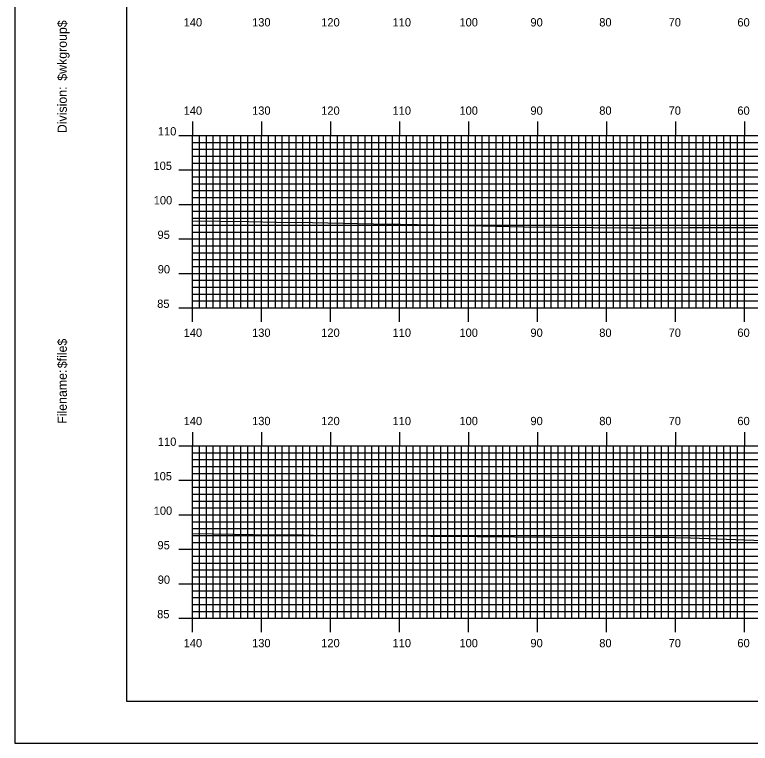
# Model space of a CAD drawing. Extents: x 1764546 to 1764889, y 442591 to 442811.
# Drawn here: x 1764545.6 to 1764652.2, y 442590.5 to 442696.2 of the extents above; entities that cross this region are included whole.
import ezdxf

# ---------------------------------------------------------------- set-up
doc = ezdxf.new("R2010")
doc.units = 0
for name, color, linetype in [('BORDER', 7, 'Continuous'), ('H_V ANNOTATION', 7, 'Continuous'), ('MAJOR', 7, 'Continuous'), ('MINOR', 7, 'Continuous'), ('PLOT BOUNDARY', 7, 'Continuous'), ('S_Roadway_Centerline', 7, 'Continuous')]:
    doc.layers.add(name, color=color, linetype=linetype)

msp = doc.modelspace()

# ---------------------------------------------------------------- linework, layer by layer
at = {"layer": 'BORDER'}
msp.add_lwpolyline([(1764561.74, 442596.67), (1764881.74, 442596.67), (1764881.74, 442806.67), (1764561.74, 442806.67)], close=True, dxfattribs=at)
at = {"layer": 'MAJOR'}
for p, q in [((1764571.34, 442680.67), (1764571.34, 442678.67)), ((1764581.34, 442680.67), (1764581.34, 442678.67)), ((1764591.34, 442680.67), (1764591.34, 442678.67)), ((1764601.34, 442680.67), (1764601.34, 442678.67)), ((1764611.34, 442680.67), (1764611.34, 442678.67)), ((1764621.34, 442680.67), (1764621.34, 442678.67)), ((1764631.34, 442680.67), (1764631.34, 442678.67)), ((1764641.34, 442680.67), (1764641.34, 442678.67)), ((1764651.34, 442680.67), (1764651.34, 442678.67)), ((1764569.34, 442678.67), (1764571.34, 442678.67)), ((1764571.34, 442678.67), (1764851.34, 442678.67)), ((1764571.34, 442653.67), (1764571.34, 442678.67)), ((1764571.34, 442653.67), (1764571.34, 442678.67)), ((1764571.34, 442678.67), (1764851.34, 442678.67)), ((1764581.34, 442653.67), (1764581.34, 442678.67)), ((1764591.34, 442653.67), (1764591.34, 442678.67)), ((1764601.34, 442653.67), (1764601.34, 442678.67)), ((1764611.34, 442653.67), (1764611.34, 442678.67)), ((1764621.34, 442653.67), (1764621.34, 442678.67)), ((1764631.34, 442653.67), (1764631.34, 442678.67)), ((1764641.34, 442653.67), (1764641.34, 442678.67)), ((1764651.34, 442653.67), (1764651.34, 442678.67)), ((1764569.34, 442673.67), (1764571.34, 442673.67)), ((1764571.34, 442673.67), (1764851.34, 442673.67)), ((1764569.34, 442668.67), (1764571.34, 442668.67)), ((1764571.34, 442668.67), (1764851.34, 442668.67)), ((1764569.34, 442663.67), (1764571.34, 442663.67)), ((1764571.34, 442663.67), (1764851.34, 442663.67)), ((1764569.34, 442658.67), (1764571.34, 442658.67)), ((1764571.34, 442658.67), (1764851.34, 442658.67)), ((1764569.34, 442653.67), (1764571.34, 442653.67)), ((1764571.34, 442653.67), (1764851.34, 442653.67)), ((1764571.34, 442653.67), (1764851.34, 442653.67)), ((1764571.34, 442651.66), (1764571.34, 442653.67)), ((1764581.34, 442651.66), (1764581.34, 442653.67)), ((1764591.34, 442651.66), (1764591.34, 442653.67)), ((1764601.34, 442651.66), (1764601.34, 442653.67)), ((1764611.34, 442651.66), (1764611.34, 442653.67)), ((1764621.34, 442651.66), (1764621.34, 442653.67)), ((1764631.34, 442651.66), (1764631.34, 442653.67)), ((1764641.34, 442651.66), (1764641.34, 442653.67)), ((1764651.34, 442651.66), (1764651.34, 442653.67)), ((1764571.34, 442635.67), (1764571.34, 442633.67)), ((1764581.34, 442635.67), (1764581.34, 442633.67)), ((1764591.34, 442635.67), (1764591.34, 442633.67)), ((1764601.34, 442635.67), (1764601.34, 442633.67)), ((1764611.34, 442635.67), (1764611.34, 442633.67)), ((1764621.34, 442635.67), (1764621.34, 442633.67)), ((1764631.34, 442635.67), (1764631.34, 442633.67)), ((1764641.34, 442635.67), (1764641.34, 442633.67)), ((1764651.34, 442635.67), (1764651.34, 442633.67)), ((1764569.34, 442633.67), (1764571.34, 442633.67)), ((1764571.34, 442633.67), (1764851.34, 442633.67)), ((1764571.34, 442608.67), (1764571.34, 442633.67)), ((1764571.34, 442608.67), (1764571.34, 442633.67)), ((1764571.34, 442633.67), (1764851.34, 442633.67)), ((1764581.34, 442608.67), (1764581.34, 442633.67)), ((1764591.34, 442608.67), (1764591.34, 442633.67)), ((1764601.34, 442608.67), (1764601.34, 442633.67)), ((1764611.34, 442608.67), (1764611.34, 442633.67)), ((1764621.34, 442608.67), (1764621.34, 442633.67)), ((1764631.34, 442608.67), (1764631.34, 442633.67)), ((1764641.34, 442608.67), (1764641.34, 442633.67)), ((1764651.34, 442608.67), (1764651.34, 442633.67)), ((1764569.34, 442628.67), (1764571.34, 442628.67)), ((1764571.34, 442628.67), (1764851.34, 442628.67)), ((1764569.34, 442623.67), (1764571.34, 442623.67)), ((1764571.34, 442623.67), (1764851.34, 442623.67)), ((1764569.34, 442618.67), (1764571.34, 442618.67)), ((1764571.34, 442618.67), (1764851.34, 442618.67)), ((1764569.34, 442613.67), (1764571.34, 442613.67)), ((1764571.34, 442613.67), (1764851.34, 442613.67)), ((1764569.34, 442608.67), (1764571.34, 442608.67)), ((1764571.34, 442608.67), (1764851.34, 442608.67)), ((1764571.34, 442608.67), (1764851.34, 442608.67)), ((1764571.34, 442606.66), (1764571.34, 442608.67)), ((1764581.34, 442606.66), (1764581.34, 442608.67)), ((1764591.34, 442606.66), (1764591.34, 442608.67)), ((1764601.34, 442606.66), (1764601.34, 442608.67)), ((1764611.34, 442606.66), (1764611.34, 442608.67)), ((1764621.34, 442606.66), (1764621.34, 442608.67)), ((1764631.34, 442606.66), (1764631.34, 442608.67)), ((1764641.34, 442606.66), (1764641.34, 442608.67)), ((1764651.34, 442606.66), (1764651.34, 442608.67))]:
    msp.add_line(p, q, dxfattribs=at)
at = {"layer": 'MINOR'}
for p, q in [((1764572.34, 442653.67), (1764572.34, 442678.67)), ((1764573.34, 442653.67), (1764573.34, 442678.67)), ((1764574.34, 442653.67), (1764574.34, 442678.67)), ((1764575.34, 442653.67), (1764575.34, 442678.67)), ((1764576.34, 442653.67), (1764576.34, 442678.67)), ((1764577.34, 442653.67), (1764577.34, 442678.67)), ((1764578.34, 442653.67), (1764578.34, 442678.67)), ((1764579.34, 442653.67), (1764579.34, 442678.67)), ((1764580.34, 442653.67), (1764580.34, 442678.67)), ((1764582.34, 442653.67), (1764582.34, 442678.67)), ((1764583.34, 442653.67), (1764583.34, 442678.67)), ((1764584.34, 442653.67), (1764584.34, 442678.67)), ((1764585.34, 442653.67), (1764585.34, 442678.67)), ((1764586.34, 442653.67), (1764586.34, 442678.67)), ((1764587.34, 442653.67), (1764587.34, 442678.67)), ((1764588.34, 442653.67), (1764588.34, 442678.67)), ((1764589.34, 442653.67), (1764589.34, 442678.67)), ((1764590.34, 442653.67), (1764590.34, 442678.67)), ((1764592.34, 442653.67), (1764592.34, 442678.67)), ((1764593.34, 442653.67), (1764593.34, 442678.67)), ((1764594.34, 442653.67), (1764594.34, 442678.67)), ((1764595.34, 442653.67), (1764595.34, 442678.67)), ((1764596.34, 442653.67), (1764596.34, 442678.67)), ((1764597.34, 442653.67), (1764597.34, 442678.67)), ((1764598.34, 442653.67), (1764598.34, 442678.67)), ((1764599.34, 442653.67), (1764599.34, 442678.67)), ((1764600.34, 442653.67), (1764600.34, 442678.67)), ((1764602.34, 442653.67), (1764602.34, 442678.67)), ((1764603.34, 442653.67), (1764603.34, 442678.67)), ((1764604.34, 442653.67), (1764604.34, 442678.67)), ((1764605.34, 442653.67), (1764605.34, 442678.67)), ((1764606.34, 442653.67), (1764606.34, 442678.67)), ((1764607.34, 442653.67), (1764607.34, 442678.67)), ((1764608.34, 442653.67), (1764608.34, 442678.67)), ((1764609.34, 442653.67), (1764609.34, 442678.67)), ((1764610.34, 442653.67), (1764610.34, 442678.67)), ((1764612.34, 442653.67), (1764612.34, 442678.67)), ((1764613.34, 442653.67), (1764613.34, 442678.67)), ((1764614.34, 442653.67), (1764614.34, 442678.67)), ((1764615.34, 442653.67), (1764615.34, 442678.67)), ((1764616.34, 442653.67), (1764616.34, 442678.67)), ((1764617.34, 442653.67), (1764617.34, 442678.67)), ((1764618.34, 442653.67), (1764618.34, 442678.67)), ((1764619.34, 442653.67), (1764619.34, 442678.67)), ((1764620.34, 442653.67), (1764620.34, 442678.67)), ((1764622.34, 442653.67), (1764622.34, 442678.67)), ((1764623.34, 442653.67), (1764623.34, 442678.67)), ((1764624.34, 442653.67), (1764624.34, 442678.67)), ((1764625.34, 442653.67), (1764625.34, 442678.67)), ((1764626.34, 442653.67), (1764626.34, 442678.67)), ((1764627.34, 442653.67), (1764627.34, 442678.67)), ((1764628.34, 442653.67), (1764628.34, 442678.67)), ((1764629.34, 442653.67), (1764629.34, 442678.67)), ((1764630.34, 442653.67), (1764630.34, 442678.67)), ((1764632.34, 442653.67), (1764632.34, 442678.67)), ((1764633.34, 442653.67), (1764633.34, 442678.67)), ((1764634.34, 442653.67), (1764634.34, 442678.67)), ((1764635.34, 442653.67), (1764635.34, 442678.67)), ((1764636.34, 442653.67), (1764636.34, 442678.67)), ((1764637.34, 442653.67), (1764637.34, 442678.67)), ((1764638.34, 442653.67), (1764638.34, 442678.67)), ((1764639.34, 442653.67), (1764639.34, 442678.67)), ((1764640.34, 442653.67), (1764640.34, 442678.67)), ((1764642.34, 442653.67), (1764642.34, 442678.67)), ((1764643.34, 442653.67), (1764643.34, 442678.67)), ((1764644.34, 442653.67), (1764644.34, 442678.67)), ((1764645.34, 442653.67), (1764645.34, 442678.67)), ((1764646.34, 442653.67), (1764646.34, 442678.67)), ((1764647.34, 442653.67), (1764647.34, 442678.67)), ((1764648.34, 442653.67), (1764648.34, 442678.67)), ((1764649.34, 442653.67), (1764649.34, 442678.67)), ((1764650.34, 442653.67), (1764650.34, 442678.67)), ((1764571.34, 442677.67), (1764851.34, 442677.67)), ((1764571.34, 442677.67), (1764573.35, 442677.67)), ((1764571.34, 442676.67), (1764851.34, 442676.67)), ((1764571.34, 442676.67), (1764573.35, 442676.67)), ((1764571.34, 442675.67), (1764851.34, 442675.67)), ((1764571.34, 442675.67), (1764573.35, 442675.67)), ((1764571.34, 442674.67), (1764851.34, 442674.67)), ((1764571.34, 442674.67), (1764573.35, 442674.67)), ((1764571.34, 442672.67), (1764851.34, 442672.67)), ((1764571.34, 442672.67), (1764573.35, 442672.67)), ((1764571.34, 442671.67), (1764851.34, 442671.67)), ((1764571.34, 442671.67), (1764573.35, 442671.67)), ((1764571.34, 442670.67), (1764851.34, 442670.67)), ((1764571.34, 442670.67), (1764573.35, 442670.67)), ((1764571.34, 442669.67), (1764851.34, 442669.67)), ((1764571.34, 442669.67), (1764573.35, 442669.67)), ((1764571.34, 442667.67), (1764851.34, 442667.67)), ((1764571.34, 442667.67), (1764573.35, 442667.67)), ((1764571.34, 442666.67), (1764851.34, 442666.67)), ((1764571.34, 442666.67), (1764573.35, 442666.67)), ((1764571.34, 442665.67), (1764851.34, 442665.67)), ((1764571.34, 442665.67), (1764573.35, 442665.67)), ((1764571.34, 442664.67), (1764851.34, 442664.67)), ((1764571.34, 442664.67), (1764573.35, 442664.67)), ((1764571.34, 442662.67), (1764851.34, 442662.67)), ((1764571.34, 442662.67), (1764573.35, 442662.67)), ((1764571.34, 442661.67), (1764851.34, 442661.67)), ((1764571.34, 442661.67), (1764573.35, 442661.67)), ((1764571.34, 442660.67), (1764851.34, 442660.67)), ((1764571.34, 442660.67), (1764573.35, 442660.67)), ((1764571.34, 442659.67), (1764851.34, 442659.67)), ((1764571.34, 442659.67), (1764573.35, 442659.67)), ((1764571.34, 442657.67), (1764851.34, 442657.67)), ((1764571.34, 442657.67), (1764573.35, 442657.67)), ((1764571.34, 442656.67), (1764851.34, 442656.67)), ((1764571.34, 442656.67), (1764573.35, 442656.67)), ((1764571.34, 442655.67), (1764851.34, 442655.67)), ((1764571.34, 442655.67), (1764573.35, 442655.67)), ((1764571.34, 442654.67), (1764851.34, 442654.67)), ((1764571.34, 442654.67), (1764573.35, 442654.67)), ((1764572.34, 442608.67), (1764572.34, 442633.67)), ((1764573.34, 442608.67), (1764573.34, 442633.67)), ((1764574.34, 442608.67), (1764574.34, 442633.67)), ((1764575.34, 442608.67), (1764575.34, 442633.67)), ((1764576.34, 442608.67), (1764576.34, 442633.67)), ((1764577.34, 442608.67), (1764577.34, 442633.67)), ((1764578.34, 442608.67), (1764578.34, 442633.67)), ((1764579.34, 442608.67), (1764579.34, 442633.67)), ((1764580.34, 442608.67), (1764580.34, 442633.67)), ((1764582.34, 442608.67), (1764582.34, 442633.67)), ((1764583.34, 442608.67), (1764583.34, 442633.67)), ((1764584.34, 442608.67), (1764584.34, 442633.67)), ((1764585.34, 442608.67), (1764585.34, 442633.67)), ((1764586.34, 442608.67), (1764586.34, 442633.67)), ((1764587.34, 442608.67), (1764587.34, 442633.67)), ((1764588.34, 442608.67), (1764588.34, 442633.67)), ((1764589.34, 442608.67), (1764589.34, 442633.67)), ((1764590.34, 442608.67), (1764590.34, 442633.67)), ((1764592.34, 442608.67), (1764592.34, 442633.67)), ((1764593.34, 442608.67), (1764593.34, 442633.67)), ((1764594.34, 442608.67), (1764594.34, 442633.67)), ((1764595.34, 442608.67), (1764595.34, 442633.67)), ((1764596.34, 442608.67), (1764596.34, 442633.67)), ((1764597.34, 442608.67), (1764597.34, 442633.67)), ((1764598.34, 442608.67), (1764598.34, 442633.67)), ((1764599.34, 442608.67), (1764599.34, 442633.67)), ((1764600.34, 442608.67), (1764600.34, 442633.67)), ((1764602.34, 442608.67), (1764602.34, 442633.67)), ((1764603.34, 442608.67), (1764603.34, 442633.67)), ((1764604.34, 442608.67), (1764604.34, 442633.67)), ((1764605.34, 442608.67), (1764605.34, 442633.67)), ((1764606.34, 442608.67), (1764606.34, 442633.67)), ((1764607.34, 442608.67), (1764607.34, 442633.67)), ((1764608.34, 442608.67), (1764608.34, 442633.67)), ((1764609.34, 442608.67), (1764609.34, 442633.67)), ((1764610.34, 442608.67), (1764610.34, 442633.67)), ((1764612.34, 442608.67), (1764612.34, 442633.67)), ((1764613.34, 442608.67), (1764613.34, 442633.67)), ((1764614.34, 442608.67), (1764614.34, 442633.67)), ((1764615.34, 442608.67), (1764615.34, 442633.67)), ((1764616.34, 442608.67), (1764616.34, 442633.67)), ((1764617.34, 442608.67), (1764617.34, 442633.67)), ((1764618.34, 442608.67), (1764618.34, 442633.67)), ((1764619.34, 442608.67), (1764619.34, 442633.67)), ((1764620.34, 442608.67), (1764620.34, 442633.67)), ((1764622.34, 442608.67), (1764622.34, 442633.67)), ((1764623.34, 442608.67), (1764623.34, 442633.67)), ((1764624.34, 442608.67), (1764624.34, 442633.67)), ((1764625.34, 442608.67), (1764625.34, 442633.67)), ((1764626.34, 442608.67), (1764626.34, 442633.67)), ((1764627.34, 442608.67), (1764627.34, 442633.67)), ((1764628.34, 442608.67), (1764628.34, 442633.67)), ((1764629.34, 442608.67), (1764629.34, 442633.67)), ((1764630.34, 442608.67), (1764630.34, 442633.67)), ((1764632.34, 442608.67), (1764632.34, 442633.67)), ((1764633.34, 442608.67), (1764633.34, 442633.67)), ((1764634.34, 442608.67), (1764634.34, 442633.67)), ((1764635.34, 442608.67), (1764635.34, 442633.67)), ((1764636.34, 442608.67), (1764636.34, 442633.67)), ((1764637.34, 442608.67), (1764637.34, 442633.67)), ((1764638.34, 442608.67), (1764638.34, 442633.67)), ((1764639.34, 442608.67), (1764639.34, 442633.67)), ((1764640.34, 442608.67), (1764640.34, 442633.67)), ((1764642.34, 442608.67), (1764642.34, 442633.67)), ((1764643.34, 442608.67), (1764643.34, 442633.67)), ((1764644.34, 442608.67), (1764644.34, 442633.67)), ((1764645.34, 442608.67), (1764645.34, 442633.67)), ((1764646.34, 442608.67), (1764646.34, 442633.67)), ((1764647.34, 442608.67), (1764647.34, 442633.67)), ((1764648.34, 442608.67), (1764648.34, 442633.67)), ((1764649.34, 442608.67), (1764649.34, 442633.67)), ((1764650.34, 442608.67), (1764650.34, 442633.67)), ((1764571.34, 442632.67), (1764851.34, 442632.67)), ((1764571.34, 442632.67), (1764573.35, 442632.67)), ((1764571.34, 442631.67), (1764851.34, 442631.67)), ((1764571.34, 442631.67), (1764573.35, 442631.67)), ((1764571.34, 442630.67), (1764851.34, 442630.67)), ((1764571.34, 442630.67), (1764573.35, 442630.67)), ((1764571.34, 442629.67), (1764851.34, 442629.67)), ((1764571.34, 442629.67), (1764573.35, 442629.67)), ((1764571.34, 442627.67), (1764851.34, 442627.67)), ((1764571.34, 442627.67), (1764573.35, 442627.67)), ((1764571.34, 442626.67), (1764851.34, 442626.67)), ((1764571.34, 442626.67), (1764573.35, 442626.67)), ((1764571.34, 442625.67), (1764851.34, 442625.67)), ((1764571.34, 442625.67), (1764573.35, 442625.67)), ((1764571.34, 442624.67), (1764851.34, 442624.67)), ((1764571.34, 442624.67), (1764573.35, 442624.67)), ((1764571.34, 442622.67), (1764851.34, 442622.67)), ((1764571.34, 442622.67), (1764573.35, 442622.67)), ((1764571.34, 442621.67), (1764851.34, 442621.67)), ((1764571.34, 442621.67), (1764573.35, 442621.67)), ((1764571.34, 442620.67), (1764851.34, 442620.67)), ((1764571.34, 442620.67), (1764573.35, 442620.67)), ((1764571.34, 442619.67), (1764851.34, 442619.67)), ((1764571.34, 442619.67), (1764573.35, 442619.67)), ((1764571.34, 442617.67), (1764851.34, 442617.67)), ((1764571.34, 442617.67), (1764573.35, 442617.67)), ((1764571.34, 442616.67), (1764851.34, 442616.67)), ((1764571.34, 442616.67), (1764573.35, 442616.67)), ((1764571.34, 442615.67), (1764851.34, 442615.67)), ((1764571.34, 442615.67), (1764573.35, 442615.67)), ((1764571.34, 442614.67), (1764851.34, 442614.67)), ((1764571.34, 442614.67), (1764573.35, 442614.67)), ((1764571.34, 442612.67), (1764851.34, 442612.67)), ((1764571.34, 442612.67), (1764573.35, 442612.67)), ((1764571.34, 442611.67), (1764851.34, 442611.67)), ((1764571.34, 442611.67), (1764573.35, 442611.67)), ((1764571.34, 442610.67), (1764851.34, 442610.67)), ((1764571.34, 442610.67), (1764573.35, 442610.67)), ((1764571.34, 442609.67), (1764851.34, 442609.67)), ((1764571.34, 442609.67), (1764573.35, 442609.67))]:
    msp.add_line(p, q, dxfattribs=at)
at = {"layer": 'PLOT BOUNDARY'}
msp.add_lwpolyline([(1764545.56, 442590.55), (1764885.56, 442590.55), (1764885.56, 442810.55), (1764545.56, 442810.55)], close=True, dxfattribs=at)
at = {"layer": 'S_Roadway_Centerline'}
for points in [[(1764571.34, 442666.31), (1764579.51, 442666.18), (1764583.53, 442666.1), (1764588.74, 442666.03), (1764597.57, 442665.87), (1764601.49, 442665.82), (1764611.43, 442665.63), (1764619.28, 442665.44), (1764629.41, 442665.34), (1764634.96, 442665.28), (1764637.33, 442665.27), (1764643.4, 442665.32), (1764655.3, 442665.32)], [(1764571.34, 442620.96), (1764580.11, 442620.84), (1764587.51, 442620.76), (1764590.29, 442620.69), (1764596.99, 442620.67), (1764603.16, 442620.64), (1764605.88, 442620.59), (1764612.62, 442620.55), (1764623.42, 442620.42), (1764627.8, 442620.37), (1764638.2, 442620.41), (1764640.34, 442620.41), (1764641.22, 442620.37), (1764643.54, 442620.32), (1764659.22, 442619.77)]]:
    msp.add_lwpolyline(points, dxfattribs=at)

# ---------------------------------------------------------------- texts
at = {"layer": 'BORDER'}
for s, p in [('$wkgroup$', (1764553.11, 442686.6)), ('Division:', (1764553.11, 442679)), ('$file$', (1764553.11, 442644.92)), ('Filename:', (1764553.11, 442636.86))]:
    msp.add_text(s, height=1.339, rotation=90, dxfattribs=at).set_placement(p)
at = {"layer": 'H_V ANNOTATION'}
for s, p in [('140', (1764570.05, 442694.47)), ('130', (1764579.97, 442694.47)), ('120', (1764589.99, 442694.47)), ('110', (1764600.33, 442694.47)), ('100', (1764610.03, 442694.47)), ('90', (1764620.32, 442694.47)), ('80', (1764630.3, 442694.47)), ('70', (1764640.35, 442694.47)), ('60', (1764650.32, 442694.47)), ('140', (1764570.05, 442681.67)), ('130', (1764579.97, 442681.67)), ('120', (1764589.99, 442681.67)), ('110', (1764600.33, 442681.67)), ('100', (1764610.03, 442681.67)), ('90', (1764620.32, 442681.67)), ('80', (1764630.3, 442681.67)), ('70', (1764640.35, 442681.67)), ('60', (1764650.32, 442681.67)), ('110', (1764566.31, 442678.67)), ('105', (1764565.68, 442673.67)), ('100', (1764565.71, 442668.67)), ('95', (1764566.26, 442663.67)), ('90', (1764566.29, 442658.67)), ('85', (1764566.21, 442653.67)), ('140', (1764570.05, 442649.47)), ('130', (1764579.97, 442649.47)), ('120', (1764589.99, 442649.47)), ('110', (1764600.33, 442649.47)), ('100', (1764610.03, 442649.47)), ('90', (1764620.32, 442649.47)), ('80', (1764630.3, 442649.47)), ('70', (1764640.35, 442649.47)), ('60', (1764650.32, 442649.47)), ('140', (1764570.05, 442636.67)), ('130', (1764579.97, 442636.67)), ('120', (1764589.99, 442636.67)), ('110', (1764600.33, 442636.67)), ('100', (1764610.03, 442636.67)), ('90', (1764620.32, 442636.67)), ('80', (1764630.3, 442636.67)), ('70', (1764640.35, 442636.67)), ('60', (1764650.32, 442636.67)), ('110', (1764566.31, 442633.67)), ('105', (1764565.68, 442628.67)), ('100', (1764565.71, 442623.67)), ('95', (1764566.26, 442618.67)), ('90', (1764566.29, 442613.67)), ('85', (1764566.21, 442608.67)), ('140', (1764570.05, 442604.47)), ('130', (1764579.97, 442604.47)), ('120', (1764589.99, 442604.47)), ('110', (1764600.33, 442604.47)), ('100', (1764610.03, 442604.47)), ('90', (1764620.32, 442604.47)), ('80', (1764630.3, 442604.47)), ('70', (1764640.35, 442604.47)), ('60', (1764650.32, 442604.47))]:
    msp.add_text(s, height=1.2, dxfattribs=at).set_placement(p)
at = {"layer": 'MAJOR'}
for p in [(1764571.34, 442653.67), (1764571.34, 442608.67)]:
    msp.add_text('-', height=0.012, dxfattribs=at).set_placement(p)

doc.saveas('drawing.dxf')
